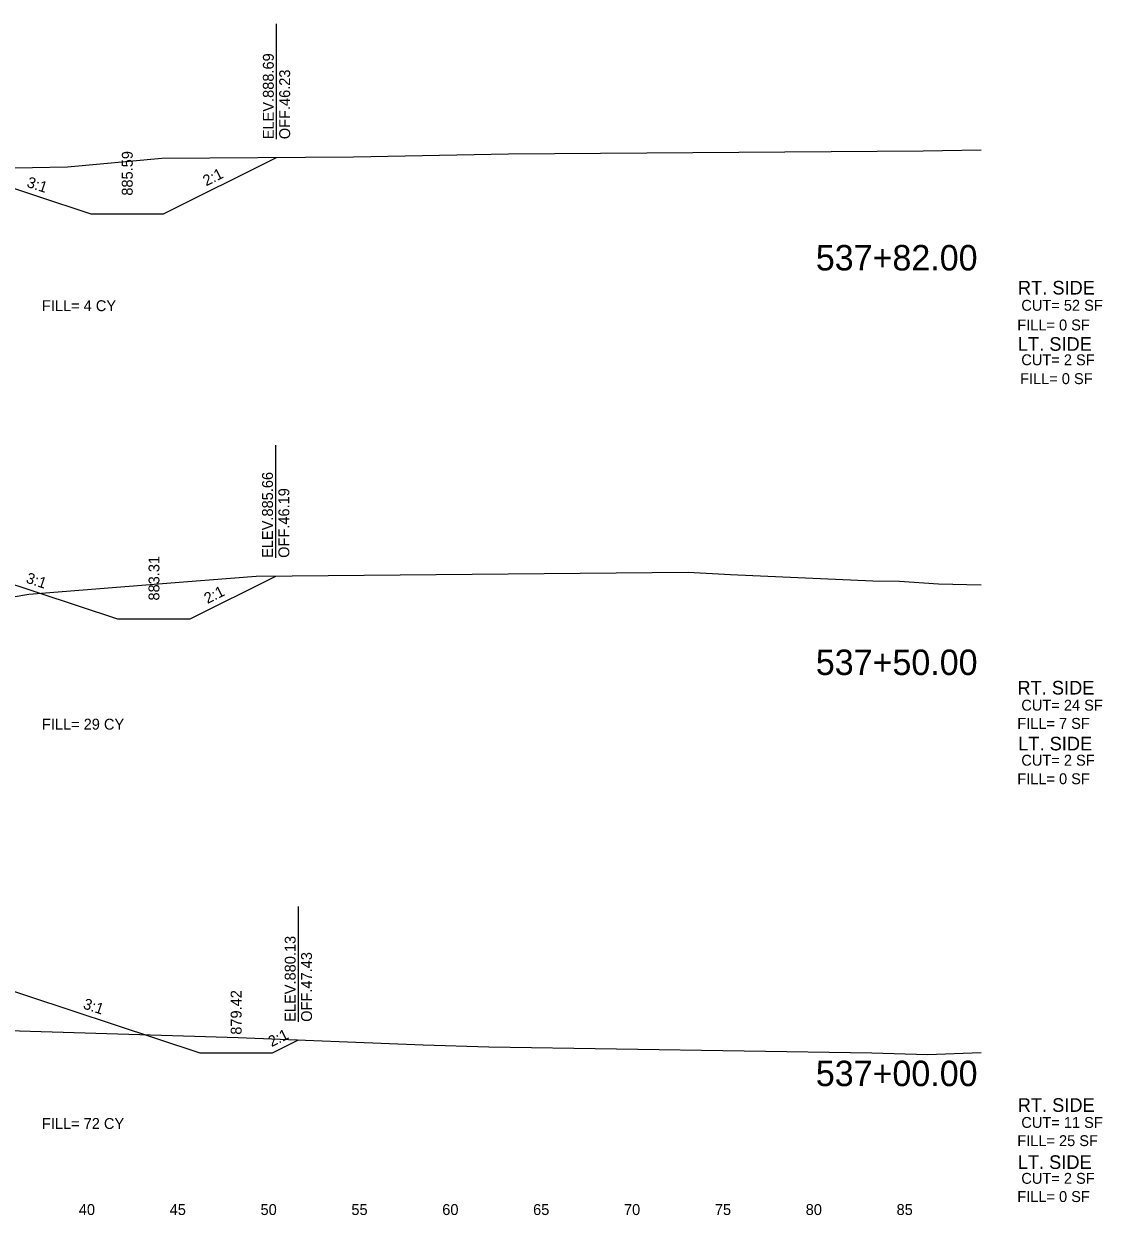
# Model space of a CAD drawing. Extents: x -4 to 359, y 0 to 1436.
# Drawn here: x 80.5 to 139.8, y 1200.5 to 1266 of the extents above; entities that cross this region are included whole.
import ezdxf

# ---------------------------------------------------------------- set-up
doc = ezdxf.new("R2010")
doc.units = 0
for name, color, linetype in [('XS-Existing surface-ground', 7, 'Continuous'), ('XS-Proposed surface-ground', 7, 'Continuous'), ('XS-Text-ditch slope', 7, 'Continuous'), ('XS-Text-earthwork labels', 7, 'Continuous'), ('XS-Text-offset label', 7, 'Continuous'), ('XS-Text-profile report', 7, 'Continuous'), ('XS-Text-tie elevation', 7, 'Continuous'), ('XS-Text-tie offset', 7, 'Continuous')]:
    doc.layers.add(name, color=color, linetype=linetype)

msp = doc.modelspace()

# ---------------------------------------------------------------- linework, layer by layer
at = {"layer": 'XS-Existing surface-ground'}
for p, q in [((82.853, 1258.131), (88.053, 1258.611)), ((88.053, 1258.611), (98.605, 1258.685)), ((98.605, 1258.685), (107.136, 1258.849)), ((107.136, 1258.849), (129.952, 1259.023)), ((129.952, 1259.023), (133.13, 1259.065)), ((77.702, 1258.049), (82.853, 1258.131)), ((93.24, 1235.612), (117.009, 1235.826)), ((117.009, 1235.826), (119.353, 1235.708)), ((119.353, 1235.708), (127.179, 1235.356)), ((80.726, 1234.624), (89.237, 1235.301)), ((89.237, 1235.301), (93.24, 1235.612)), ((127.179, 1235.356), (128.646, 1235.334)), ((128.646, 1235.334), (130.797, 1235.193)), ((130.797, 1235.193), (133.13, 1235.135)), ((77.453, 1234.084), (80.726, 1234.624)), ((77.615, 1210.676), (92.244, 1210.228)), ((92.244, 1210.228), (102.433, 1209.821)), ((102.433, 1209.821), (106.044, 1209.724)), ((106.044, 1209.724), (127.121, 1209.386)), ((130.193, 1209.303), (133.13, 1209.407)), ((127.121, 1209.386), (130.193, 1209.303))]:
    msp.add_line(p, q, dxfattribs=at)
at = {"layer": 'XS-Proposed surface-ground'}
for p, q in [((78.104, 1235.753), (85.619, 1233.273)), ((89.619, 1233.273), (94.316, 1235.621)), ((85.619, 1233.273), (89.619, 1233.273))]:
    msp.add_line(p, q, dxfattribs=at)
for points in [[(78.149, 1257.529), (84.149, 1255.549), (88.149, 1255.549), (94.361, 1258.655)], [(78.359, 1213.283), (90.14, 1209.384), (94.14, 1209.384), (95.564, 1210.095)]]:
    msp.add_lwpolyline(points, dxfattribs=at)
at = {"layer": 'XS-Text-tie offset'}
for p, q in [((94.361, 1259.655), (94.361, 1266.005)), ((94.316, 1236.621), (94.316, 1242.822)), ((95.564, 1211.095), (95.564, 1217.445))]:
    msp.add_line(p, q, dxfattribs=at)

# ---------------------------------------------------------------- texts
at = {"layer": 'XS-Text-ditch slope'}
for s, rotation, p in [('2:1', 26.56505, (90.495, 1257.058)), ('3:1', 341.73711, (80.578, 1257.044)), ('3:1', 341.73711, (80.533, 1235.267)), ('2:1', 26.56505, (90.563, 1234.081)), ('3:1', 341.68679, (83.679, 1211.838)), ('2:1', 26.56505, (94.091, 1209.695))]:
    msp.add_text(s, height=0.6, rotation=rotation, dxfattribs=at).set_placement(p)
at = {"layer": 'XS-Text-earthwork labels'}
for s, height, p in [('RT. SIDE', 0.75, (135.161, 1251.112)), ('FILL= 4 CY           ', 0.6, (81.452, 1250.196)), (' CUT= 52 SF           ', 0.6, (135.125, 1250.218)), ('FILL= 0 SF           ', 0.6, (135.125, 1249.136)), ('LT. SIDE', 0.75, (135.161, 1248.015)), (' CUT= 2 SF           ', 0.6, (135.125, 1247.219)), ('FILL= 0 SF           ', 0.6, (135.278, 1246.183)), ('RT. SIDE', 0.75, (135.134, 1229.103)), (' CUT= 24 SF           ', 0.6, (135.125, 1228.216)), ('FILL= 29 CY           ', 0.6, (81.452, 1227.17)), ('FILL= 7 SF           ', 0.6, (135.125, 1227.213)), ('LT. SIDE', 0.75, (135.179, 1226.028)), (' CUT= 2 SF           ', 0.6, (135.125, 1225.187)), ('FILL= 0 SF           ', 0.6, (135.125, 1224.168)), ('RT. SIDE', 0.75, (135.149, 1206.141)), ('FILL= 72 CY           ', 0.6, (81.452, 1205.199)), (' CUT= 11 SF           ', 0.6, (135.125, 1205.257)), ('FILL= 25 SF           ', 0.6, (135.125, 1204.255)), ('LT. SIDE', 0.75, (135.149, 1202.999)), (' CUT= 2 SF           ', 0.6, (135.125, 1202.182)), ('FILL= 0 SF           ', 0.6, (135.125, 1201.179))]:
    msp.add_text(s, height=height, dxfattribs=at).set_placement(p)
at = {"layer": 'XS-Text-offset label'}
for s, height, p in [('           537+82.00           ', 1.4, (118.317, 1252.436)), ('           537+50.00           ', 1.4, (118.317, 1230.176)), ('           537+00.00           ', 1.4, (118.317, 1207.555)), ('           40           ', 0.6, (81.03, 1200.464)), ('           45           ', 0.6, (86.03, 1200.464)), ('           50           ', 0.6, (91.03, 1200.464)), ('           55           ', 0.6, (96.03, 1200.464)), ('           60           ', 0.6, (101.03, 1200.464)), ('           65           ', 0.6, (106.03, 1200.464)), ('           70           ', 0.6, (111.03, 1200.464)), ('           75           ', 0.6, (116.03, 1200.464)), ('           80           ', 0.6, (121.03, 1200.464)), ('           85           ', 0.6, (126.03, 1200.464))]:
    msp.add_text(s, height=height, dxfattribs=at).set_placement(p)
at = {"layer": 'XS-Text-profile report'}
for s, p in [('Dtch_Bkslp_1_T', (94.35, 1258.654)), ('Rt_Agg_Layer_1_B13', (81.629, 1256.375)), ('Dtch_Frslp_1_B', (84.138, 1255.549)), ('Dtch_Bkslp_1_B', (88.138, 1255.549)), ('Dtch_Bkslp_1_T', (94.304, 1235.621)), ('Rt_Agg_Layer_1_B13', (81.584, 1234.599)), ('Dtch_Frslp_1_B', (85.607, 1233.272)), ('Dtch_Bkslp_1_B', (89.607, 1233.272)), ('Rt_Agg_Layer_1_B13', (81.828, 1212.129)), ('Dtch_Bkslp_1_T', (95.552, 1210.095)), ('Dtch_Frslp_1_B', (90.129, 1209.383)), ('Dtch_Bkslp_1_B', (94.129, 1209.383))]:
    msp.add_text(s, height=0.00167, dxfattribs=at).set_placement(p)
at = {"layer": 'XS-Text-tie elevation'}
for s, p in [('ELEV.888.69', (94.211, 1259.655)), ('OFF.46.23', (95.111, 1259.655)), ('885.59', (86.449, 1256.549)), ('ELEV.885.66', (94.166, 1236.621)), ('OFF.46.19', (95.066, 1236.621)), ('883.31', (87.919, 1234.273)), ('ELEV.880.13', (95.414, 1211.095)), ('OFF.47.43', (96.314, 1211.095)), ('879.42', (92.44, 1210.384))]:
    msp.add_text(s, height=0.6, rotation=90, dxfattribs=at).set_placement(p)

doc.saveas('drawing.dxf')
